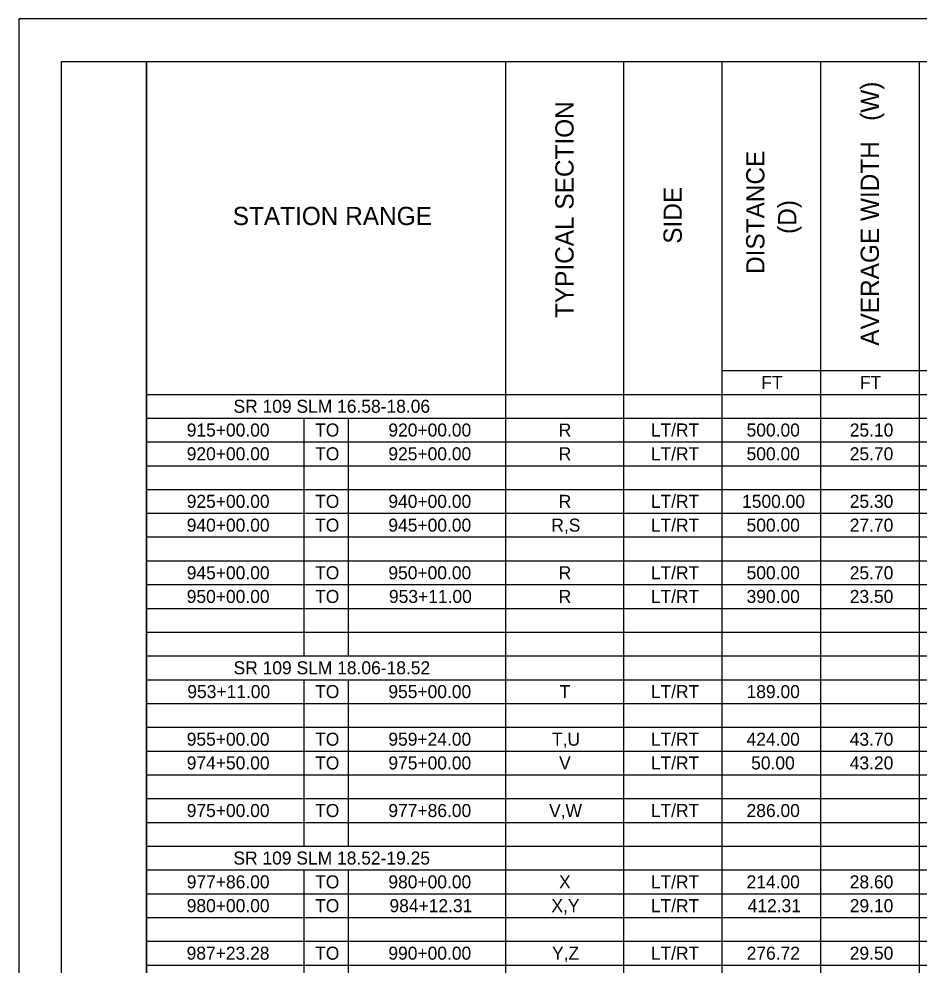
# Model space of a CAD drawing. Extents: x 0 to 34, y 0 to 22.
# Drawn here: x 0 to 10.58, y 10.87 to 22 of the extents above; entities that cross this region are included whole.
import ezdxf

# ---------------------------------------------------------------- set-up
doc = ezdxf.new("R2010")
doc.units = 0
for name, color, linetype in [('SH_Border', 7, 'Continuous'), ('SH_Cut_Line', 7, 'Continuous'), ('SH_Text', 7, 'Continuous')]:
    doc.layers.add(name, color=color, linetype=linetype)

msp = doc.modelspace()

# ---------------------------------------------------------------- linework, layer by layer
at = {"layer": 'SH_Border'}
for points in [[(0.5, 21.5), (1.5, 21.5), (1.5, 0.5), (0.5, 0.5)], [(1.5, 21.5), (33.5, 21.5), (33.5, 0.5), (1.5, 0.5)]]:
    msp.add_lwpolyline(points, close=True, dxfattribs=at)
at = {"layer": 'SH_Cut_Line'}
msp.add_lwpolyline([(0, 0), (34, 0), (34, 22), (0, 22)], close=True, dxfattribs=at)
at = {"layer": 'SH_Text'}
for p, q in [((1.5, 21.5), (3.871, 21.5)), ((1.5, 21.5), (1.5, 21.22)), ((3.871, 21.5), (8.267, 21.5)), ((5.722, 21.5), (5.722, 21.22)), ((7.108, 21.5), (7.108, 21.22)), ((8.267, 21.5), (10.584, 21.5)), ((8.267, 21.5), (8.267, 21.22)), ((9.425, 21.5), (9.425, 21.22)), ((10.584, 21.5), (11.743, 21.5)), ((10.584, 21.5), (10.584, 21.22)), ((1.5, 21.22), (1.5, 20.941)), ((5.722, 21.22), (5.722, 20.941)), ((7.108, 21.22), (7.108, 20.941)), ((8.267, 21.22), (8.267, 20.941)), ((9.425, 21.22), (9.425, 20.941)), ((10.584, 21.22), (10.584, 20.941)), ((1.5, 20.941), (1.5, 20.661)), ((5.722, 20.941), (5.722, 20.661)), ((7.108, 20.941), (7.108, 20.661)), ((8.267, 20.941), (8.267, 20.661)), ((9.425, 20.941), (9.425, 20.661)), ((10.584, 20.941), (10.584, 20.661)), ((1.5, 20.661), (1.5, 20.381)), ((5.722, 20.661), (5.722, 20.381)), ((7.108, 20.661), (7.108, 20.381)), ((8.267, 20.661), (8.267, 20.381)), ((9.425, 20.661), (9.425, 20.381)), ((10.584, 20.661), (10.584, 20.381)), ((1.5, 20.381), (1.5, 20.101)), ((5.722, 20.381), (5.722, 20.101)), ((7.108, 20.381), (7.108, 20.101)), ((8.267, 20.381), (8.267, 20.101)), ((9.425, 20.381), (9.425, 20.101)), ((10.584, 20.381), (10.584, 20.101)), ((1.5, 20.101), (1.5, 19.822)), ((5.722, 20.101), (5.722, 19.822)), ((7.108, 20.101), (7.108, 19.822)), ((8.267, 20.101), (8.267, 19.822)), ((9.425, 20.101), (9.425, 19.822)), ((10.584, 20.101), (10.584, 19.822)), ((1.5, 19.822), (1.5, 19.542)), ((5.722, 19.822), (5.722, 19.542)), ((7.108, 19.822), (7.108, 19.542)), ((8.267, 19.822), (8.267, 19.542)), ((9.425, 19.822), (9.425, 19.542)), ((10.584, 19.822), (10.584, 19.542)), ((1.5, 19.542), (1.5, 19.262)), ((5.722, 19.542), (5.722, 19.262)), ((7.108, 19.542), (7.108, 19.262)), ((8.267, 19.542), (8.267, 19.262)), ((9.425, 19.542), (9.425, 19.262)), ((10.584, 19.542), (10.584, 19.262)), ((1.5, 19.262), (1.5, 18.983)), ((5.722, 19.262), (5.722, 18.983)), ((7.108, 19.262), (7.108, 18.983)), ((8.267, 19.262), (8.267, 18.983)), ((9.425, 19.262), (9.425, 18.983)), ((10.584, 19.262), (10.584, 18.983)), ((1.5, 18.983), (1.5, 18.703)), ((5.722, 18.983), (5.722, 18.703)), ((7.108, 18.983), (7.108, 18.703)), ((8.267, 18.983), (8.267, 18.703)), ((9.425, 18.983), (9.425, 18.703)), ((10.584, 18.983), (10.584, 18.703)), ((1.5, 18.703), (1.5, 18.423)), ((5.722, 18.703), (5.722, 18.423)), ((7.108, 18.703), (7.108, 18.423)), ((8.267, 18.703), (8.267, 18.423)), ((9.425, 18.703), (9.425, 18.423)), ((10.584, 18.703), (10.584, 18.423)), ((1.5, 18.423), (1.5, 18.143)), ((5.722, 18.423), (5.722, 18.143)), ((7.108, 18.423), (7.108, 18.143)), ((8.267, 18.423), (8.267, 18.143)), ((9.425, 18.423), (9.425, 18.143)), ((10.584, 18.423), (10.584, 18.143)), ((1.5, 18.143), (1.5, 17.864)), ((5.722, 18.143), (5.722, 17.864)), ((7.108, 18.143), (7.108, 17.864)), ((8.267, 18.143), (8.267, 17.864)), ((9.425, 18.143), (9.425, 17.864)), ((10.584, 18.143), (10.584, 17.864)), ((1.5, 17.864), (1.5, 17.584)), ((5.722, 17.864), (5.722, 17.584)), ((7.108, 17.864), (7.108, 17.584)), ((8.267, 17.864), (10.584, 17.864)), ((8.267, 17.864), (8.267, 17.584)), ((9.425, 17.864), (9.425, 17.584)), ((10.584, 17.864), (11.743, 17.864)), ((10.584, 17.864), (10.584, 17.584)), ((1.5, 17.584), (3.871, 17.584)), ((1.5, 17.584), (1.5, 17.304)), ((3.871, 17.584), (8.267, 17.584)), ((5.722, 17.584), (5.722, 17.304)), ((7.108, 17.584), (7.108, 17.304)), ((8.267, 17.584), (10.584, 17.584)), ((8.267, 17.584), (8.267, 17.304)), ((9.425, 17.584), (9.425, 17.304)), ((10.584, 17.584), (11.743, 17.584)), ((10.584, 17.584), (10.584, 17.304)), ((1.5, 17.304), (3.871, 17.304)), ((1.5, 17.304), (1.5, 17.024)), ((3.351, 17.304), (3.351, 17.024)), ((3.871, 17.304), (8.267, 17.304)), ((3.871, 17.304), (3.871, 17.024)), ((5.722, 17.304), (5.722, 17.024)), ((7.108, 17.304), (7.108, 17.024)), ((8.267, 17.304), (10.584, 17.304)), ((8.267, 17.304), (8.267, 17.024)), ((9.425, 17.304), (9.425, 17.024)), ((10.584, 17.304), (11.743, 17.304)), ((10.584, 17.304), (10.584, 17.024)), ((1.5, 17.024), (3.871, 17.024)), ((1.5, 17.024), (1.5, 16.745)), ((3.351, 17.024), (3.351, 16.745)), ((3.871, 17.024), (8.267, 17.024)), ((3.871, 17.024), (3.871, 16.745)), ((5.722, 17.024), (5.722, 16.745)), ((7.108, 17.024), (7.108, 16.745)), ((8.267, 17.024), (10.584, 17.024)), ((8.267, 17.024), (8.267, 16.745)), ((9.425, 17.024), (9.425, 16.745)), ((10.584, 17.024), (11.743, 17.024)), ((10.584, 17.024), (10.584, 16.745)), ((1.5, 16.745), (3.871, 16.745)), ((1.5, 16.745), (1.5, 16.465)), ((3.351, 16.745), (3.351, 16.465)), ((3.871, 16.745), (8.267, 16.745)), ((3.871, 16.745), (3.871, 16.465)), ((5.722, 16.745), (5.722, 16.465)), ((7.108, 16.745), (7.108, 16.465)), ((8.267, 16.745), (10.584, 16.745)), ((8.267, 16.745), (8.267, 16.465)), ((9.425, 16.745), (9.425, 16.465)), ((10.584, 16.745), (11.743, 16.745)), ((10.584, 16.745), (10.584, 16.465)), ((1.5, 16.465), (3.871, 16.465)), ((1.5, 16.465), (1.5, 16.185)), ((3.351, 16.465), (3.351, 16.185)), ((3.871, 16.465), (8.267, 16.465)), ((3.871, 16.465), (3.871, 16.185)), ((5.722, 16.465), (5.722, 16.185)), ((7.108, 16.465), (7.108, 16.185)), ((8.267, 16.465), (10.584, 16.465)), ((8.267, 16.465), (8.267, 16.185)), ((9.425, 16.465), (9.425, 16.185)), ((10.584, 16.465), (11.743, 16.465)), ((10.584, 16.465), (10.584, 16.185)), ((1.5, 16.185), (3.871, 16.185)), ((1.5, 16.185), (1.5, 15.906)), ((3.351, 16.185), (3.351, 15.906)), ((3.871, 16.185), (8.267, 16.185)), ((3.871, 16.185), (3.871, 15.906)), ((5.722, 16.185), (5.722, 15.906)), ((7.108, 16.185), (7.108, 15.906)), ((8.267, 16.185), (10.584, 16.185)), ((8.267, 16.185), (8.267, 15.906)), ((9.425, 16.185), (9.425, 15.906)), ((10.584, 16.185), (11.743, 16.185)), ((10.584, 16.185), (10.584, 15.906)), ((1.5, 15.906), (3.871, 15.906)), ((1.5, 15.906), (1.5, 15.626)), ((3.351, 15.906), (3.351, 15.626)), ((3.871, 15.906), (8.267, 15.906)), ((3.871, 15.906), (3.871, 15.626)), ((5.722, 15.906), (5.722, 15.626)), ((7.108, 15.906), (7.108, 15.626)), ((8.267, 15.906), (10.584, 15.906)), ((8.267, 15.906), (8.267, 15.626)), ((9.425, 15.906), (9.425, 15.626)), ((10.584, 15.906), (11.743, 15.906)), ((10.584, 15.906), (10.584, 15.626)), ((1.5, 15.626), (3.871, 15.626)), ((1.5, 15.626), (1.5, 15.346)), ((3.351, 15.626), (3.351, 15.346)), ((3.871, 15.626), (8.267, 15.626)), ((3.871, 15.626), (3.871, 15.346)), ((5.722, 15.626), (5.722, 15.346)), ((7.108, 15.626), (7.108, 15.346)), ((8.267, 15.626), (10.584, 15.626)), ((8.267, 15.626), (8.267, 15.346)), ((9.425, 15.626), (9.425, 15.346)), ((10.584, 15.626), (11.743, 15.626)), ((10.584, 15.626), (10.584, 15.346)), ((1.5, 15.346), (3.871, 15.346)), ((1.5, 15.346), (1.5, 15.066)), ((3.351, 15.346), (3.351, 15.066)), ((3.871, 15.346), (8.267, 15.346)), ((3.871, 15.346), (3.871, 15.066)), ((5.722, 15.346), (5.722, 15.066)), ((7.108, 15.346), (7.108, 15.066)), ((8.267, 15.346), (10.584, 15.346)), ((8.267, 15.346), (8.267, 15.066)), ((9.425, 15.346), (9.425, 15.066)), ((10.584, 15.346), (11.743, 15.346)), ((10.584, 15.346), (10.584, 15.066)), ((1.5, 15.066), (3.871, 15.066)), ((1.5, 15.066), (1.5, 14.787)), ((3.351, 15.066), (3.351, 14.787)), ((3.871, 15.066), (8.267, 15.066)), ((3.871, 15.066), (3.871, 14.787)), ((5.722, 15.066), (5.722, 14.787)), ((7.108, 15.066), (7.108, 14.787)), ((8.267, 15.066), (10.584, 15.066)), ((8.267, 15.066), (8.267, 14.787)), ((9.425, 15.066), (9.425, 14.787)), ((10.584, 15.066), (11.743, 15.066)), ((10.584, 15.066), (10.584, 14.787)), ((1.5, 14.787), (3.871, 14.787)), ((1.5, 14.787), (1.5, 14.507)), ((3.351, 14.787), (3.351, 14.507)), ((3.871, 14.787), (8.267, 14.787)), ((3.871, 14.787), (3.871, 14.507)), ((5.722, 14.787), (5.722, 14.507)), ((7.108, 14.787), (7.108, 14.507)), ((8.267, 14.787), (10.584, 14.787)), ((8.267, 14.787), (8.267, 14.507)), ((9.425, 14.787), (9.425, 14.507)), ((10.584, 14.787), (11.743, 14.787)), ((10.584, 14.787), (10.584, 14.507)), ((1.5, 14.507), (3.871, 14.507)), ((1.5, 14.507), (1.5, 14.227)), ((3.871, 14.507), (8.267, 14.507)), ((5.722, 14.507), (5.722, 14.227)), ((7.108, 14.507), (7.108, 14.227)), ((8.267, 14.507), (10.584, 14.507)), ((8.267, 14.507), (8.267, 14.227)), ((9.425, 14.507), (9.425, 14.227)), ((10.584, 14.507), (11.743, 14.507)), ((10.584, 14.507), (10.584, 14.227)), ((1.5, 14.227), (3.871, 14.227)), ((1.5, 14.227), (1.5, 13.948)), ((3.351, 14.227), (3.351, 13.948)), ((3.871, 14.227), (8.267, 14.227)), ((3.871, 14.227), (3.871, 13.948)), ((5.722, 14.227), (5.722, 13.948)), ((7.108, 14.227), (7.108, 13.948)), ((8.267, 14.227), (10.584, 14.227)), ((8.267, 14.227), (8.267, 13.948)), ((9.425, 14.227), (9.425, 13.948)), ((10.584, 14.227), (11.743, 14.227)), ((10.584, 14.227), (10.584, 13.948)), ((1.5, 13.948), (3.871, 13.948)), ((1.5, 13.948), (1.5, 13.668)), ((3.351, 13.948), (3.351, 13.668)), ((3.871, 13.948), (8.267, 13.948)), ((3.871, 13.948), (3.871, 13.668)), ((5.722, 13.948), (5.722, 13.668)), ((7.108, 13.948), (7.108, 13.668)), ((8.267, 13.948), (10.584, 13.948)), ((8.267, 13.948), (8.267, 13.668)), ((9.425, 13.948), (9.425, 13.668)), ((10.584, 13.948), (11.743, 13.948)), ((10.584, 13.948), (10.584, 13.668)), ((1.5, 13.668), (3.871, 13.668)), ((1.5, 13.668), (1.5, 13.388)), ((3.351, 13.668), (3.351, 13.388)), ((3.871, 13.668), (8.267, 13.668)), ((3.871, 13.668), (3.871, 13.388)), ((5.722, 13.668), (5.722, 13.388)), ((7.108, 13.668), (7.108, 13.388)), ((8.267, 13.668), (10.584, 13.668)), ((8.267, 13.668), (8.267, 13.388)), ((9.425, 13.668), (9.425, 13.388)), ((10.584, 13.668), (11.743, 13.668)), ((10.584, 13.668), (10.584, 13.388)), ((1.5, 13.388), (3.871, 13.388)), ((1.5, 13.388), (1.5, 13.108)), ((3.351, 13.388), (3.351, 13.108)), ((3.871, 13.388), (8.267, 13.388)), ((3.871, 13.388), (3.871, 13.108)), ((5.722, 13.388), (5.722, 13.108)), ((7.108, 13.388), (7.108, 13.108)), ((8.267, 13.388), (10.584, 13.388)), ((8.267, 13.388), (8.267, 13.108)), ((9.425, 13.388), (9.425, 13.108)), ((10.584, 13.388), (11.743, 13.388)), ((10.584, 13.388), (10.584, 13.108)), ((1.5, 13.108), (3.871, 13.108)), ((1.5, 13.108), (1.5, 12.829)), ((3.351, 13.108), (3.351, 12.829)), ((3.871, 13.108), (8.267, 13.108)), ((3.871, 13.108), (3.871, 12.829)), ((5.722, 13.108), (5.722, 12.829)), ((7.108, 13.108), (7.108, 12.829)), ((8.267, 13.108), (10.584, 13.108)), ((8.267, 13.108), (8.267, 12.829)), ((9.425, 13.108), (9.425, 12.829)), ((10.584, 13.108), (11.743, 13.108)), ((10.584, 13.108), (10.584, 12.829)), ((1.5, 12.829), (3.871, 12.829)), ((1.5, 12.829), (1.5, 12.549)), ((3.351, 12.829), (3.351, 12.549)), ((3.871, 12.829), (8.267, 12.829)), ((3.871, 12.829), (3.871, 12.549)), ((5.722, 12.829), (5.722, 12.549)), ((7.108, 12.829), (7.108, 12.549)), ((8.267, 12.829), (10.584, 12.829)), ((8.267, 12.829), (8.267, 12.549)), ((9.425, 12.829), (9.425, 12.549)), ((10.584, 12.829), (11.743, 12.829)), ((10.584, 12.829), (10.584, 12.549)), ((1.5, 12.549), (3.871, 12.549)), ((1.5, 12.549), (1.5, 12.269)), ((3.351, 12.549), (3.351, 12.269)), ((3.871, 12.549), (8.267, 12.549)), ((3.871, 12.549), (3.871, 12.269)), ((5.722, 12.549), (5.722, 12.269)), ((7.108, 12.549), (7.108, 12.269)), ((8.267, 12.549), (10.584, 12.549)), ((8.267, 12.549), (8.267, 12.269)), ((9.425, 12.549), (9.425, 12.269)), ((10.584, 12.549), (11.743, 12.549)), ((10.584, 12.549), (10.584, 12.269)), ((1.5, 12.269), (3.871, 12.269)), ((1.5, 12.269), (1.5, 11.99)), ((3.871, 12.269), (8.267, 12.269)), ((5.722, 12.269), (5.722, 11.99)), ((7.108, 12.269), (7.108, 11.99)), ((8.267, 12.269), (10.584, 12.269)), ((8.267, 12.269), (8.267, 11.99)), ((9.425, 12.269), (9.425, 11.99)), ((10.584, 12.269), (11.743, 12.269)), ((10.584, 12.269), (10.584, 11.99)), ((1.5, 11.99), (3.871, 11.99)), ((1.5, 11.99), (1.5, 11.71)), ((3.351, 11.99), (3.351, 11.71)), ((3.871, 11.99), (8.267, 11.99)), ((3.871, 11.99), (3.871, 11.71)), ((5.722, 11.99), (5.722, 11.71)), ((7.108, 11.99), (7.108, 11.71)), ((8.267, 11.99), (10.584, 11.99)), ((8.267, 11.99), (8.267, 11.71)), ((9.425, 11.99), (9.425, 11.71)), ((10.584, 11.99), (11.743, 11.99)), ((10.584, 11.99), (10.584, 11.71)), ((1.5, 11.71), (3.871, 11.71)), ((1.5, 11.71), (1.5, 11.43)), ((3.351, 11.71), (3.351, 11.43)), ((3.871, 11.71), (8.267, 11.71)), ((3.871, 11.71), (3.871, 11.43)), ((5.722, 11.71), (5.722, 11.43)), ((7.108, 11.71), (7.108, 11.43)), ((8.267, 11.71), (10.584, 11.71)), ((8.267, 11.71), (8.267, 11.43)), ((9.425, 11.71), (9.425, 11.43)), ((10.584, 11.71), (11.743, 11.71)), ((10.584, 11.71), (10.584, 11.43)), ((1.5, 11.43), (3.871, 11.43)), ((1.5, 11.43), (1.5, 11.15)), ((3.351, 11.43), (3.351, 11.15)), ((3.871, 11.43), (8.267, 11.43)), ((3.871, 11.43), (3.871, 11.15)), ((5.722, 11.43), (5.722, 11.15)), ((7.108, 11.43), (7.108, 11.15)), ((8.267, 11.43), (10.584, 11.43)), ((8.267, 11.43), (8.267, 11.15)), ((9.425, 11.43), (9.425, 11.15)), ((10.584, 11.43), (11.743, 11.43)), ((10.584, 11.43), (10.584, 11.15)), ((1.5, 11.15), (3.871, 11.15)), ((1.5, 11.15), (1.5, 10.871)), ((3.351, 11.15), (3.351, 10.871)), ((3.871, 11.15), (8.267, 11.15)), ((3.871, 11.15), (3.871, 10.871)), ((5.722, 11.15), (5.722, 10.871)), ((7.108, 11.15), (7.108, 10.871)), ((8.267, 11.15), (10.584, 11.15)), ((8.267, 11.15), (8.267, 10.871)), ((9.425, 11.15), (9.425, 10.871)), ((10.584, 11.15), (11.743, 11.15)), ((10.584, 11.15), (10.584, 10.871)), ((1.5, 10.871), (3.871, 10.871)), ((1.5, 10.871), (1.5, 10.591)), ((3.351, 10.871), (3.351, 10.591)), ((3.871, 10.871), (8.267, 10.871)), ((3.871, 10.871), (3.871, 10.591)), ((5.722, 10.871), (5.722, 10.591)), ((7.108, 10.871), (7.108, 10.591)), ((8.267, 10.871), (10.584, 10.871)), ((8.267, 10.871), (8.267, 10.591)), ((9.425, 10.871), (9.425, 10.591)), ((10.584, 10.871), (11.743, 10.871)), ((10.584, 10.871), (10.584, 10.591))]:
    msp.add_line(p, q, dxfattribs=at)

# ---------------------------------------------------------------- texts
for s, height, p in [('AVERAGE WIDTH   (W)', 0.21445, (10.112, 18.156)), ('TYPICAL SECTION', 0.21445, (6.522, 18.482)), ('DISTANCE                                                                                                        ', 0.214452, (8.766, 19)), ('SIDE', 0.2145, (7.794, 19.356)), ('(D)', 0.2145, (9.141, 19.471))]:
    msp.add_text(s, height=height, rotation=90, dxfattribs=at).set_placement(p)
for s, height, p in [('STATION RANGE', 0.21445, (2.514, 19.575)), ('FT', 0.1532, (8.73, 17.647)), ('FT', 0.1532, (9.889, 17.647)), ('SR 109 SLM 16.58-18.06', 0.15318, (2.523, 17.367)), ('915+00.00', 0.1532, (1.973, 17.088)), ('TO', 0.1532, (3.483, 17.088)), ('920+00.00', 0.1532, (4.344, 17.088)), ('R', 0.153, (6.347, 17.088)), ('LT/RT', 0.1532, (7.43, 17.088)), ('500.00', 0.1532, (8.556, 17.088)), ('25.10', 0.1532, (9.769, 17.088)), ('920+00.00', 0.1532, (1.973, 16.808)), ('TO', 0.1532, (3.483, 16.808)), ('925+00.00', 0.1532, (4.344, 16.808)), ('R', 0.153, (6.347, 16.808)), ('LT/RT', 0.1532, (7.43, 16.808)), ('500.00', 0.1532, (8.556, 16.808)), ('25.70', 0.1532, (9.769, 16.808)), ('925+00.00', 0.1532, (1.973, 16.249)), ('TO', 0.1532, (3.483, 16.249)), ('940+00.00', 0.1532, (4.344, 16.249)), ('R', 0.153, (6.347, 16.249)), ('LT/RT', 0.1532, (7.43, 16.249)), ('1500.00', 0.1532, (8.503, 16.249)), ('25.30', 0.1532, (9.769, 16.249)), ('940+00.00', 0.1532, (1.973, 15.969)), ('TO', 0.1532, (3.483, 15.969)), ('945+00.00', 0.1532, (4.344, 15.969)), ('R,S', 0.1532, (6.26, 15.969)), ('LT/RT', 0.1532, (7.43, 15.969)), ('500.00', 0.1532, (8.556, 15.969)), ('27.70', 0.1532, (9.769, 15.969)), ('945+00.00', 0.1532, (1.973, 15.409)), ('TO', 0.1532, (3.483, 15.409)), ('950+00.00', 0.1532, (4.344, 15.409)), ('R', 0.153, (6.347, 15.409)), ('LT/RT', 0.1532, (7.43, 15.409)), ('500.00', 0.1532, (8.556, 15.409)), ('25.70', 0.1532, (9.769, 15.409)), ('950+00.00', 0.1532, (1.973, 15.13)), ('TO', 0.1532, (3.483, 15.13)), ('953+11.00', 0.1532, (4.351, 15.13)), ('R', 0.153, (6.347, 15.13)), ('LT/RT', 0.1532, (7.43, 15.13)), ('390.00', 0.1532, (8.556, 15.13)), ('23.50', 0.1532, (9.769, 15.13)), ('SR 109 SLM 18.06-18.52', 0.15318, (2.524, 14.291)), ('953+11.00', 0.1532, (1.98, 14.011)), ('TO', 0.1532, (3.483, 14.011)), ('955+00.00', 0.1532, (4.344, 14.011)), ('T', 0.153, (6.358, 14.011)), ('LT/RT', 0.1532, (7.43, 14.011)), ('189.00', 0.1532, (8.556, 14.011)), ('955+00.00', 0.1532, (1.973, 13.451)), ('TO', 0.1532, (3.483, 13.451)), ('959+24.00', 0.1532, (4.344, 13.451)), ('T,U', 0.1532, (6.268, 13.451)), ('LT/RT', 0.1532, (7.43, 13.451)), ('424.00', 0.1532, (8.556, 13.451)), ('43.70', 0.1532, (9.769, 13.451)), ('974+50.00', 0.1532, (1.973, 13.172)), ('TO', 0.1532, (3.483, 13.172)), ('975+00.00', 0.1532, (4.344, 13.172)), ('V', 0.153, (6.352, 13.172)), ('LT/RT', 0.1532, (7.43, 13.172)), ('50.00', 0.1532, (8.61, 13.172)), ('43.20', 0.1532, (9.769, 13.172)), ('975+00.00', 0.1532, (1.973, 12.612)), ('TO', 0.1532, (3.483, 12.612)), ('977+86.00', 0.1532, (4.344, 12.612)), ('V,W', 0.1532, (6.234, 12.612)), ('LT/RT', 0.1532, (7.43, 12.612)), ('286.00', 0.1532, (8.556, 12.612)), ('SR 109 SLM 18.52-19.25', 0.15318, (2.522, 12.053)), ('977+86.00', 0.1532, (1.973, 11.773)), ('TO', 0.1532, (3.483, 11.773)), ('980+00.00', 0.1532, (4.344, 11.773)), ('X', 0.153, (6.351, 11.773)), ('LT/RT', 0.1532, (7.43, 11.773)), ('214.00', 0.1532, (8.556, 11.773)), ('28.60', 0.1532, (9.769, 11.773)), ('980+00.00', 0.1532, (1.973, 11.493)), ('TO', 0.1532, (3.483, 11.493)), ('984+12.31', 0.1532, (4.357, 11.493)), ('X,Y', 0.1532, (6.261, 11.493)), ('LT/RT', 0.1532, (7.43, 11.493)), ('412.31', 0.1532, (8.569, 11.493)), ('29.10', 0.1532, (9.769, 11.493)), ('987+23.28', 0.1532, (1.972, 10.934)), ('TO', 0.1532, (3.483, 10.934)), ('990+00.00', 0.1532, (4.344, 10.934)), ('Y,Z', 0.1532, (6.268, 10.934)), ('LT/RT', 0.1532, (7.43, 10.934)), ('276.72', 0.1532, (8.557, 10.934)), ('29.50', 0.1532, (9.769, 10.934))]:
    msp.add_text(s, height=height, dxfattribs=at).set_placement(p)

doc.saveas('drawing.dxf')
